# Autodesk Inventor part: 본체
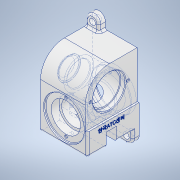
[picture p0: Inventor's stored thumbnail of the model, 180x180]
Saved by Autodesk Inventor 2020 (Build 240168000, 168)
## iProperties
Created: 2023-09
Part Number: 본체
Material: 알루미늄 6061
Document SubType Name: Modeling
Designer: oem
Density: 2.7 g/cm^3
Appearance: 알루미늄 - 평지
Mass: 945.161 g
Surface Area: 634.589 cm^2
Volume: 350.06 cm^3
Author: oem
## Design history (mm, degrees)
sketch "스케치1"
  geometry: L1 (-34.5, 40)-(34.5, 40); L2 (34.5, 40)-(34.5, -40); L3 (34.5, -40)-(-34.5, -40); L4 (-34.5, -40)-(-34.5, 40); L5 (-34.5, 40)-(34.5, -40); L6 (34.5, 40)-(-34.5, -40); 1 further point
  constraints: 12 end point, 2 midpoint, 2 parallel, 1 horizontal, 1 perpendicular
  dimensions: "d0" = 80 distance of L1.end L2.end; "d1" = 69 distance of L1.start L1.end
extrude "돌출1" new body sketch "스케치1" stored distance "d2" = 72; taper "d3" = 0 deg
sketch "스케치2"
  geometry: L1 (34.5, 40)-(34.5, -40) reference; L2 (34.5, 40)-(34.5, 40); L3 (71.5, 3)-(71.5, -40); L4 (71.5, -40)-(34.5, -40); L5 (34.5, -40)-(34.5, 40); A1 r 37 centre (34.5, 3) between (71.5, 3) and (34.5, 40); 4 further points
  constraints: 8 end point, 2 parallel, 2 point on circle, 2 point on line, 2 tangent, 1 centre point, 1 horizontal, 1 perpendicular
  dimensions: "d4" = 80 distance of point (71.5, 40) L3.end; "d5" = 37 distance of L1.start point (71.5, 40); "d6" = 37 radius of A1
extrude "돌출2" join sketch "스케치2" stored distance "d7" = 72; taper "d8" = 0 deg
sketch "스케치3"
  geometry: L1 (40, 71.5)-(-3, 71.5) reference; L2 (40, -34.5)-(-40, -34.5) reference; L3 (40, -34.5)-(-40, -34.5); L4 (-40, -34.5)-(-40, -0.5); L5 (-40, -0.5)-(40, -0.5); L6 (40, -0.5)-(40, -34.5); L7 (-40, -34.5)-(40, -34.5) reference; L8 (40, -34.5)-(40, 71.5) reference; L9 (40, 71.5)-(-3, 71.5) reference; L10 (-40, 34.5)-(-40, -34.5) reference; L11 (-40, -0.5)-(40, -0.5); L12 (40, -34.5)-(40, 71.5) reference; L13 (40, 71.5)-(-3, 71.5); L14 (-40, 34.5)-(-40, -4.319); L15 (-40, 34.5)-(-40, -34.5) reference; L16 (-3, 71.5)-(40, 71.5) reference; L17 (-3, 71.5)-(-3, 71.5); L18 (40, 71.5)-(40, -0.5); A1 r 37 centre (-3, 34.5) between (-3, 71.5) and (-40, 34.5) reference; A2 r 37 centre (-3, 34.5) between (-3, 71.5) and (-40, 34.5) reference; A3 r 37 centre (-3, 34.5) between (-3, 71.5) and (-40, 34.5); 5 further points
  constraints: 18 end point, 4 point on line, 3 collinear, 3 point on circle, 2 parallel, 2 perpendicular, 2 tangent, 1 centre point, 1 horizontal
  dimensions: "d10" = 72 distance between parallel lines of L1 L5; "d11" = 37 radius of A3 (derived)
extrude "돌출3" cut sketch "스케치3" distance "d12" = 3; taper "d13" = 0 deg
sketch "스케치5"
  geometry: L1 (-11, -14.5)-(5, -14.5); L2 (5, -14.5)-(5, -34.5); L3 (5, -34.5)-(-11, -34.5); L4 (-11, -34.5)-(-11, -14.5); L5 (-40, -34.5)-(40, -34.5) reference; A1 r 37 centre (-3, 34.5) between (-3, 71.5) and (-40, 34.5) reference; 1 further point
  constraints: 8 end point, 2 parallel, 1 collinear, 1 horizontal, 1 midpoint, 1 perpendicular, 1 vertical alignment
  dimensions: "d25" = 16 distance of L2.end L3.end; "d26" = 20 distance of L1.end L2.end
sketch "스케치6"
  geometry: L1 (72, 0)-(0, 0) reference; L2 (0, 0)-(72, 0); L3 (72, 0)-(72, -10); L4 (62, -20)-(10, -20); L5 (0, -10)-(0, 0); A1 r 10 centre (10, -10) between (0, -10) and (10, -20); A2 r 10 centre (62, -10) between (62, -20) and (72, -10); 4 further points
  constraints: 8 end point, 4 point on circle, 4 point on line, 4 tangent, 2 centre point, 2 parallel, 1 equal radius, 1 horizontal, 1 perpendicular
  dimensions: "d20" = 72 distance of point (72, -20) point (0, -20); "d21" = 20 distance of point (0, -20) L1.end; "d22" = 10 radius of A1
extrude "돌출5" join sketch "스케치6" distance "d23" = 10; taper "d24" = 0 deg
extrude "돌출6" cut sketch "스케치5" stored distance "d27" = 10; taper "d28" = 0 deg
sketch "스케치9"
  geometry: L1 (0, 43)-(69, 43) reference; L2 (0, 0)-(0, 43) reference; L3 (10, 43)-(0, 43) reference; L4 (0, 43)-(20, 43); L5 (20, 43)-(20, 33); L6 (20, 33)-(0, 33); L7 (0, 33)-(0, 43); 3 further points
  constraints: 8 end point, 2 parallel, 1 horizontal, 1 perpendicular
  dimensions: "d29" = 10 distance of L4.end L5.end; "d30" = 20 distance of L5.end L6.end
extrude "돌출7" join sketch "스케치9" distance "d31" = 20; taper "d32" = 0 deg
fillet "모깎기1" dims "d33" = 10
sketch "스케치12"
  geometry: C1 r 4.5 at (10, 10); A1 r 10 centre (10, 10) between (20, 10) and (0, 10) reference; 1 further point
  constraints: 1 centre point, 1 coincident
  dimensions: "d35" = 9 diameter of C1
extrude "돌출8" cut sketch "스케치12" distance "d36" = 20; taper "d37" = 0 deg
sketch "스케치13"
  geometry: C1 r 4.5 at (-62, -10); C2 r 4.5 at (-10, -10); A1 r 10 centre (-10, -10) between (-10, -20) and (0, -10) reference; A2 r 10 centre (-62, -10) between (-72, -10) and (-62, -20) reference; 1 further point
  constraints: 2 centre point, 2 coincident
  dimensions: "d38" = 9 diameter of C1; "d39" = 9 diameter of C2
extrude "돌출9" cut sketch "스케치13" distance "d40" = 20; taper "d41" = 0 deg
sketch "스케치14"
  geometry: L1 (-34.5, 40)-(34.5, 40) reference; L2 (-44.5, -40)-(81.5, -40) reference; L3 (0.5, 40)-(0.5, -40); L4 (-34.5, 11)-(-34.5, 40) reference; L5 (0.5, 40)-(32, 40); L6 (32, 37)-(23, 37); L7 (32, 37)-(32, 40); L8 (23, 37)-(23, 25); L9 (23, 25)-(0.5, 25); L10 (23, -32)-(23, -20); L11 (23, -20)-(0.5, -20); L12 (19, -20)-(19, 25); L13 (32, -32)-(32, -40); L14 (32, -40)-(0.5, -40); L15 (32, -32)-(23, -32); 3 further points
  constraints: 24 end point, 10 point on line, 6 perpendicular, 4 vertical, 1 collinear
  dimensions: "d49" = 35 distance between parallel lines of L3 L4; "d52" = 12 distance of L6.end L8.end; "d55" = 45 diameter of L8 L3; "d60" = 45 diameter of L10 L3; "d61" = 37 diameter of L12 L3; "d62" = 63 diameter of L7 L3; "d63" = 3 distance of L6.start L5.end; "d64" = 63 diameter of L13 L3; "d65" = 8 distance between parallel lines of L2 L15; "d66" = 12 distance between parallel lines of L15 L11
revolve "회전1" sketch "스케치14" stored, may be unused: angle "d67" = 90 deg
chamfer "모따기2" distance "d84" = 1; stored, may be unused: second distance "d85" = 2, angle "d86" = 45 deg
sketch "스케치17"
  geometry: C1 r 22.5 at (0, 0) reference; C2 r 30.5 at (0, 0) reference; A1 r 26 centre (0, 0) between (0, 26) and (0, -26)
  constraints: 2 point on circle, 2 vertical alignment, 1 centre point, 1 coincident
  dimensions: "d90" = 52 diameter of A1
hole "구멍1" sketch "스케치17" at (0, 26), (0, -26) diameter "d91" = 3.242; stored, may be unused: countersink angle "d95" = 60 deg, drill point angle "d97" = 118 deg; dims "d92" = 8, "d93" = 4.25, "d94" = 2, "d96" = 10
sketch "스케치18" dims "d99" = 52
  geometry: C1 r 22.5 at (0, 0) reference; C2 r 30.5 at (0, 0) reference; C3 r 22.5 at (0, 0) reference; C4 r 1.621 at (0, -26) reference; 3 further points
  constraints: 3 vertical alignment, 2 coincident, 2 other
hole "구멍2" sketch "스케치18" at (0, -26), (0, 26) diameter "d100" = 3.242; stored, may be unused: countersink angle "d104" = 60 deg, drill point angle "d106" = 118 deg; dims "d101" = 8, "d102" = 4.25, "d103" = 2, "d105" = 10
node "작업 평면2"
sketch "스케치19"
  geometry: L1 (69, 69)-(0, 69); L2 (72, 0)-(0, 0) reference; L3 (69, 106)-(69, 34) reference; L4 (62, 94)-(62, 92); L5 (62, 92)-(22, 92); L6 (22, 92)-(22, 87.5); L7 (21, 86.5)-(7.3, 86.5); L8 (7, 86.2)-(7, 84.5); L9 (7, 84.5)-(3, 84.5); L10 (3, 84.5)-(3, 69); L11 (62, 94)-(69, 94); L12 (69, 94)-(69, 69); L13 (21, 86.5)-(22, 87.5); A1 r 0.3 centre (7.3, 86.2) between (7.3, 86.5) and (7, 86.2); 3 further points
  constraints: 22 end point, 7 perpendicular, 7 point on line, 2 point on circle, 2 tangent, 1 centre point, 1 collinear, 1 horizontal, 1 vertical
  dimensions: "d124" = 69 distance between parallel lines of L2 L1; "d137" = 31 diameter of L9 L1; "d138" = 35 diameter of L7 L1; "d139" = 46 diameter of L5 L1; "d140" = 50 diameter of L11 L1; "d141" = 7 distance of L4.start L11.end; "d142" = 40 distance of L4.end L5.end; "d143" = 4 distance of L8.end L9.end; "d144" = 15 distance of point (22, 86.5) point (7, 86.5); "d145" = 0.3 radius of A1 (derived); "d146" = 1 distance of L7.start point (22, 86.5); "d147" = 1 distance of L6.end point (22, 86.5) (= d146)
revolve "회전3" sketch "스케치19" stored, may be unused: angle "d136" = 90 deg
chamfer "모따기3" distance "d148" = 1; stored, may be unused: second distance "d149" = 2, angle "d150" = 45 deg
sketch "스케치20"
  geometry: C1 r 26 at (-3, 34.5) reference; A1 r 37 centre (-3, 34.5) between (-3, 71.5) and (-40, 34.5) reference; A2 r 29 centre (-3, 34.5) between (26, 34.5) and (-32, 34.5); 1 further point
  constraints: 2 horizontal alignment, 2 point on circle, 1 centre point, 1 coincident
  dimensions: "d151" = 58 diameter of A2
hole "구멍3" sketch "스케치20" at (26, 34.5), (-32, 34.5) diameter "d152" = 3.242; stored, may be unused: countersink angle "d156" = 60 deg, drill point angle "d158" = 118 deg; dims "d153" = 8, "d154" = 4.25, "d155" = 2, "d157" = 10
node "작업 평면3"
sketch "스케치21"
  geometry: L1 (-40, -34.5)-(-11, -34.5) reference; C1 r 26 at (-3, 34.5) reference; 2 further points
  constraints: 1 vertical alignment, 1 other
  dimensions: "d160" = 27 distance from line of L1 point (-3, -7.5)
feature "엠보싱1" sketch "스케치21" dims "d0" = 80, "d1" = 69, "d161" = 0.5, "d162" = 0
fillet "모깎기2" dims "d172" = 3
fillet "모깎기3" dims "d173" = 3
fillet "모깎기4" dims "d174" = 3
fillet "모깎기5" dims "d175" = 3
sketch "스케치23"
  geometry: L1 (-3, 8)-(-72, 8) reference; L2 (-72, 0)-(-72, 16) reference; L3 (-10, -17)-(-10, 33) reference; L4 (-10, -15)-(-10, 31) reference; L5 (-50, 0.993)-(-50, 15.007) reference; 4 further points
  constraints: 2 point on line, 1 midpoint, 1 vertical alignment
  dimensions: "d179" = 50 distance of point (-61, 8) point (-11, 8); "d180" = 25 horizontal distance of point (-36, 5) point (-11, 8)
hole "구멍5" sketch "스케치23" at (-11, 8), (-61, 8) diameter "d181" = 3.242; stored, may be unused: countersink angle "d185" = 60 deg, drill point angle "d187" = 118 deg; dims "d182" = 8, "d183" = 4.25, "d184" = 2, "d186" = 10
fillet "모깎기6" dims "d188" = 3
node "솔리드1"
node "투영된 루프1"
node "투영된 루프2"
feature "A9D066F2-1C7D-4E18-AEED-F7BC21143FA4" dims "d91" = 3.242, "d92" = 8, "d93" = 4.25, "d94" = 2, "d95" = 60 deg, "d96" = 10, "d97" = 118 deg
other parameters: "d109" = -37, "d159" = 5
